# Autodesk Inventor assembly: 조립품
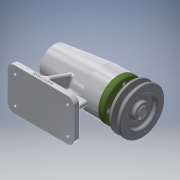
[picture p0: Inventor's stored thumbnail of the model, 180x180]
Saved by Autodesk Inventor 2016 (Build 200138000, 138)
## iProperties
Created: 2018-09
Part Number: 조립품
Document SubType Name: Assembly
Designer: CAMTIC
Author: CAMTIC
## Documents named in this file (12)
- C:\Users\CAMTIC\Desktop\480907V1028\조립품.iam
- C:\Users\CAMTIC\Desktop\480907V1028\본체.ipt
- C:\Users\CAMTIC\Desktop\480907V1028\V벨트풀리.ipt
- C:\Users\CAMTIC\Desktop\480907V1028\멈춤나사 M3.ipt
- C:\Users\CAMTIC\Desktop\480907V1028\베어링 6004.ipt
- C:\Users\CAMTIC\Desktop\480907V1028\베어링 51202.ipt
- C:\Users\CAMTIC\Desktop\480907V1028\볼트 M4.ipt
- C:\Users\CAMTIC\Desktop\480907V1028\어댑터슬리브.ipt
- C:\Users\CAMTIC\Desktop\480907V1028\오일 실.ipt
- C:\Users\CAMTIC\Desktop\480907V1028\축.ipt
- C:\Users\CAMTIC\Desktop\480907V1028\커버.ipt
- C:\Users\CAMTIC\Desktop\480907V1028\키 5 x 5 x 16.ipt
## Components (1 placed, 1 different names)
1. V벨트풀리:1 — 플러쉬:1
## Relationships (1: Flush 1)
- 플러쉬:1 [Flush]: V벨트풀리:1
